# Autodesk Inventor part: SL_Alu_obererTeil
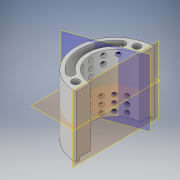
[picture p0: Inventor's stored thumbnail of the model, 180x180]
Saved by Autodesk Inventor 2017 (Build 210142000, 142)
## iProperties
Part Number: SL_Alu_obererTeil
Material: Generisch
Document SubType Name: Modeling
Designer: gabriel
Density: 1 g/cm^3
Appearance: Vorgabe
Author: gabriel
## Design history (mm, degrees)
sketch "Skizze1"
  geometry: L1 (16.2, 0)-(-2.7, 0) reference; L2 (0, -25.2)-(0, 4.2) reference; L3 (8.5, 0)-(8.5, -21); L4 (8.5, -21)-(13.5, -21); L5 (13.5, -21)-(13.5, 0); L6 (13.5, 0)-(8.5, 0); 1 further point
  constraints: 8 end point, 2 point on line, 1 horizontal, 1 parallel, 1 perpendicular, 1 vertical
  dimensions: "d0" = 8.5 distance of point (0, 0) L3.start; "d1" = 21 distance of L4.end L5.end; "d2" = 5 distance of L3.start L5.end
revolve "Umdrehung1" sketch "Skizze1" stored, may be unused: angle "d3" = 90 deg
sketch "Skizze2"
  geometry: L1 (-18.9, 0)-(18.9, 0) reference; L2 (0, -18.9)-(0, 18.9) reference; L3 (0.2, -13.5)-(-0.2, -13.5); L4 (-0.005, 13.5)-(0.005, 13.5); L5 (0.005, 13.5)-(0.005, -13.5); L6 (0.005, -13.5)-(-0.005, -13.5); L7 (-0.005, -13.5)-(-0.005, 13.5); C1 r 13.5 at (0, 0) reference; 1 further point
  constraints: 10 end point, 2 parallel, 2 tangent, 1 horizontal, 1 perpendicular, 1 other
  dimensions: "d9" = 0.01 distance of L4.start L4.end
extrude "Extrusion2" cut sketch "Skizze2" distance "d7" = 21; taper "d8" = 0 deg
sketch "Skizze3"
  geometry: L1 (-5.464, -9.465)-(-5.464, -9.465); L2 (-5.464, 9.465)-(-5.464, 9.465); L3 (-18.9, 0)-(18.9, 0) reference; L4 (0, -18.9)-(0, 18.9) reference; L5 (0, 0)-(-9.378, 16.243); L6 (0, 0)-(-8.82, -15.276); A1 r 9.75 centre (0, 0) between (-5.803, 7.835) and (-5.803, -7.835); A2 r 12.25 centre (0, 0) between (-7.291, 9.844) and (-7.291, -9.844); A3 r 1.25 centre (-6.547, 8.84) between (-5.464, 9.465) and (-7.291, 9.844); A4 r 1.25 centre (-6.547, 8.84) between (-5.803, 7.835) and (-5.464, 9.465); A5 r 1.25 centre (-6.547, -8.84) between (-7.291, -9.844) and (-5.464, -9.465); A6 r 1.25 centre (-6.547, -8.84) between (-5.464, -9.465) and (-5.803, -7.835); 5 further points
  constraints: 16 point on circle, 8 end point, 8 tangent, 6 centre point, 5 point on line, 2 coincident, 2 equal radius, 2 other
  dimensions: "d10" = 120 deg angle of L1 L2; "d11" = 9.75 radius of A1; "d12" = 12.25 radius of A2; "d13" = 1.25 radius of A3; "d14" = 1.25 radius of A4; "d112" = 120 deg angle of L6 L5
workplane "Arbeitsebene1"
extrude "Extrusion3" cut sketch "Skizze3" distance "d16" = 8; taper "d17" = 0 deg
sketch "Skizze4"
  geometry: L1 (18.9, 0)-(-18.9, 0) reference; L2 (0, -24.499)-(0, 26.867) reference; L3 (1.898, -10.763)-(1.898, -10.763); L4 (1.898, 10.763)-(1.898, 10.763); L5 (0, 0)-(3.444, 19.529); L6 (0, 0)-(3.026, -17.161); A1 r 9.75 centre (0, 0) between (2.773, -9.347) and (2.773, 9.347); A2 r 12.25 centre (0, 0) between (3.484, -11.744) and (3.484, 11.744); A3 r 1.25 centre (3.129, 10.546) between (3.484, 11.744) and (1.898, 10.763); A4 r 1.25 centre (3.129, 10.546) between (1.898, 10.763) and (2.773, 9.347); A5 r 1.25 centre (3.129, -10.546) between (2.773, -9.347) and (1.898, -10.763); A6 r 1.25 centre (3.129, -10.546) between (1.898, -10.763) and (3.484, -11.744); 5 further points
  constraints: 16 point on circle, 8 end point, 8 tangent, 6 centre point, 5 point on line, 3 equal radius, 2 coincident, 2 collinear, 3 other
  dimensions: "d19" = 12.25 radius of A2; "d20" = 9.75 radius of A1; "d21" = 1.25 radius of A3; "d52" = 160 deg angle of L5 L6
extrude "Extrusion4" cut sketch "Skizze4" distance "d22" = 10; taper "d23" = 0 deg
workplane "Arbeitsebene2"
sketch "Skizze5"
  geometry: L1 (18.9, 0)-(-18.9, 0) reference; L2 (0, -18.9)-(0, 18.9) reference; C1 r 12.25 at (0, 0); A1 r 12.25 centre (0, 0) between (3.484, -11.744) and (3.484, 11.744) reference; 1 further point
  constraints: 1 centre point, 1 coincident, 1 concentric
extrude "Extrusion5" cut sketch "Skizze5" distance "d24" = 1; taper "d25" = 0 deg
sketch "Skizze6"
  geometry: L1 (0, -18.9)-(0, 18.9) reference; L2 (-18.9, 0)-(18.9, 0) reference; A1 r 1.25 centre (-3.129, 10.546) between (-2.773, 9.347) and (-3.484, 11.744) reference; A2 r 1.25 centre (-3.129, -10.546) between (-3.484, -11.744) and (-2.773, -9.347) reference; 3 further points
  constraints: 1 coincident, 1 symmetric about line
hole "Bohrung1" sketch "Skizze6" at (-3.129, -10.546), (-3.129, 10.546) diameter "d27" = 2.5; stored, may be unused: countersink angle "d31" = 90 deg, drill point angle "d33" = 118 deg; dims "d28" = 6, "d29" = 4, "d30" = 2, "d32" = 19
sketch "Skizze11"
  geometry: L1 (0, -18.9)-(0, 18.9) reference; L2 (-18.9, 0)-(18.9, 0) reference; L3 (0, 14)-(14, 14); L4 (14, 14)-(14, -14.5); L5 (14, -14.5)-(0, -14.5); L6 (0, -14.5)-(0, 14); 1 further point
  constraints: 8 end point, 2 parallel, 1 horizontal, 1 perpendicular, 1 point on line
extrude "Extrusion6" cut sketch "Skizze11" stored distance "d64" = 10; taper "d65" = 0 deg
sketch "Skizze12"
  geometry: L1 (20, -17)-(20, 0) reference; L2 (20, 0)-(0, 0) reference; L3 (0, -17)-(0, 0) reference; L4 (0, -17)-(20, -17) reference; L5 (25.2, -8.5)-(-4.2, -8.5) reference; L6 (0, -27.4)-(0, 10.4) reference; 4 further points
  constraints: 3 point on line
  dimensions: "d69" = 1.5 distance from line of L1 point (18.5, -8.5); "d136" = 6.5 distance from line of point (13.5, -8.5) L1; "d137" = 4 distance from line of point (16, -8.5) L1
hole "Bohrung2" sketch "Skizze12" at (18.5, -8.5), (16, -8.5), (13.5, -8.5) diameter "d72" = 1.5; stored, may be unused: countersink angle "d76" = 90 deg, drill point angle "d78" = 118 deg; dims "d73" = 6, "d74" = 4, "d75" = 2, "d77" = 8
pattern_circular "Runde Anordnung4" dims angle "d80" = 130 deg
sketch "Skizze13"
  geometry: L1 (20, -17)-(20, 0) reference; L2 (20, 0)-(0, 0) reference; L3 (0, -17)-(0, 0) reference; L4 (0, -17)-(20, -17) reference; L5 (25.2, -8.5)-(-4.2, -8.5) reference; L6 (0, -27.4)-(0, 10.4) reference; 9 further points
  constraints: 1 point on line, 7 other
  dimensions: "d82" = 1.5 distance of point (0, -8.5) point (1.5, -8.5)
  node "Projizierte Kontur2"
sketch "Skizze14"
  geometry: L1 (20, -17)-(20, 0) reference; L2 (20, 0)-(0, 0) reference; L3 (0, -17)-(0, 0) reference; L4 (0, -17)-(20, -17) reference; L5 (25.2, -8.5)-(-4.2, -8.5) reference; L6 (0, -27.4)-(0, 10.4) reference; 9 further points
  constraints: 1 point on line, 7 other
  dimensions: "d83" = 4 distance from line of L3 point (4, -8.5)
  node "Projizierte Kontur3"
sketch "Skizze15"
  geometry: L1 (20, -17)-(20, 0) reference; L2 (20, 0)-(0, 0) reference; L3 (0, -17)-(0, 0) reference; L4 (0, -17)-(20, -17) reference; L5 (25.2, -8.5)-(-4.2, -8.5) reference; L6 (0, -27.4)-(0, 10.4) reference; 9 further points
  constraints: 1 point on line, 7 other
  dimensions: "d84" = 6.5 distance from line of L3 point (6.5, -8.5)
hole "Bohrung3" sketch "Skizze15" at (6.5, -8.5) diameter "d85" = 1.5; stored, may be unused: countersink angle "d89" = 90 deg, drill point angle "d91" = 118 deg; dims "d86" = 6, "d87" = 4, "d88" = 2, "d90" = 8
hole "Bohrung4" sketch "Skizze14" diameter "d92" = 1.5; stored, may be unused: countersink angle "d96" = 90 deg, drill point angle "d98" = 118 deg; dims "d93" = 6, "d94" = 4, "d95" = 2, "d97" = 8
hole "Bohrung5" sketch "Skizze13" diameter "d99" = 1.5; stored, may be unused: countersink angle "d103" = 90 deg, drill point angle "d105" = 118 deg; dims "d100" = 6, "d101" = 4, "d102" = 2, "d104" = 8
pattern_circular "Runde Anordnung5" dims angle "d107" = 100 deg
pattern_circular "Runde Anordnung6" dims angle "d110" = 50 deg
sketch "Skizze16"
  geometry: L1 (0, -18.9)-(0, 18.9) reference; L2 (16.2, 0)-(-2.7, 0) reference; 2 further points
  constraints: 1 point on line
  dimensions: "d113" = 12.875 distance from line of L1 point (12.875, 0)
hole "Bohrung6" sketch "Skizze16" at (12.875, 0) diameter "d114" = 0.5; stored, may be unused: countersink angle "d118" = 90 deg, drill point angle "d120" = 118 deg; dims "d115" = 6, "d116" = 4, "d117" = 2, "d119" = 4
workplane "Arbeitsebene3"
sketch "Skizze17"
  geometry: L1 (-14.7, -2.902)-(14.7, -2.902) reference; L2 (10.5, -24.589)-(10.5, 6.093) reference; L3 (10.5, -24.589)-(10.5, 6.093) reference; L4 (-9.5, 0)-(-9.5, -11.402) reference; 4 further points
  dimensions: "d124" = 4 distance from line of L4 point (-5.5, -3.5); "d125" = 6.5 distance from line of point (-3, -3.5) L4
hole "Bohrung7" sketch "Skizze17" at (-5.5, -3.5), (-3, -3.5) diameter "d126" = 1.5; stored, may be unused: countersink angle "d130" = 90 deg, drill point angle "d132" = 0 deg; dims "d127" = 6, "d128" = 4, "d129" = 2, "d131" = 8
pattern_circular "Runde Anordnung7" dims angle "d134" = 230 deg
node "Volumenkörper1"
node "Projizierte Kontur1"
node "Projizierte Kontur4"
other parameters: "d15" = -10.5, "d123" = 110 deg
